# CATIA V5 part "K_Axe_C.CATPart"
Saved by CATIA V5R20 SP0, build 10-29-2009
Part number: Axe_C
Bounding box of the stored display mesh (mm): x -22.5 to 22.5, y -22.49 to 22.49, z 0 to 144.581
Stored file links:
  G:\Khaled_CFAO_2011\ST2M\ST2M_GR2\echouteau\Khaled\CAD_ThinkMotion\K_Axe_C.CATPart
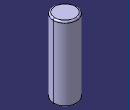
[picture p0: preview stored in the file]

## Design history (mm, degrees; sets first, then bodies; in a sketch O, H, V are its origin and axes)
AxisSystem1: origin (0, 0, 0), X (1, 0, 0), Y (0, 1, 0), Z (0, 0, 1)
Body1 (main body)
  Sketch1 on XY plane of AxisSystem1, origin (0, 0, 0), H (1, 0, 0), V (0, 1, 0)
    circle A1 centre (0, 0) radius 22.5
    radius A1 = 22.5
  Pad1: profile Sketch1, direction (0, 0, 1), length 144.581
  Fillet1: radius 3, on end face of Pad1
  Fillet2: radius 3, on edge [start face of Pad1 | face of Pad1 from Sketch1.A1]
